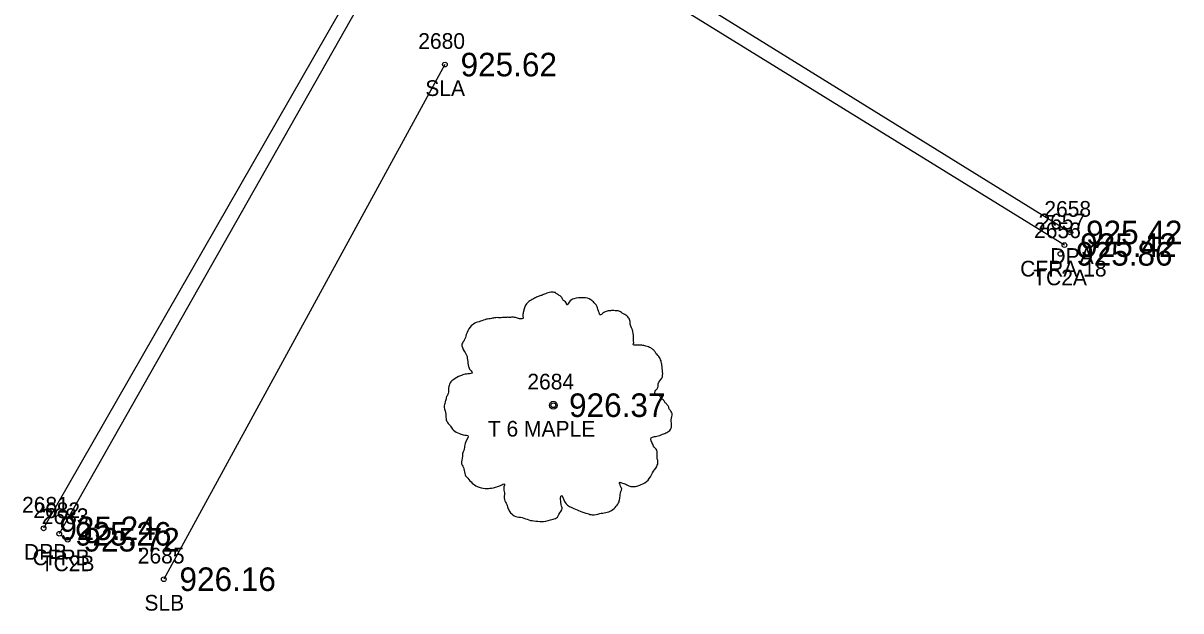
# Model space of a CAD drawing. Extents: x 1575382 to 1578175, y 1099175 to 1101955.
# Drawn here: x 1576884.4 to 1576958.1, y 1100231.2 to 1100268.6 of the extents above; entities that cross this region are included whole.
import ezdxf

# ---------------------------------------------------------------- set-up
doc = ezdxf.new("R2010")
doc.units = 0
for name, color, linetype in [('RD_EX_Conc', 7, 'Continuous'), ('RD_EX_Conc_txCode', 7, 'Continuous'), ('RD_EX_Driveway', 7, 'Continuous'), ('RD_EX_Driveway_txCode', 7, 'Continuous'), ('RD_EX_TX_Conc_ELEV', 7, 'Continuous'), ('RD_EX_TX_Driveway_ELEV', 7, 'Continuous'), ('RD_EX_TX_VEG_ELEV', 7, 'Continuous'), ('RD_EX_VEG', 7, 'Continuous'), ('RD_EX_VEG_txCode', 7, 'Continuous'), ('RD_SMD_Locator', 7, 'Continuous')]:
    doc.layers.add(name, color=color, linetype=linetype)

msp = doc.modelspace()

# ---------------------------------------------------------------- linework, layer by layer
at = {"layer": 'RD_EX_Conc'}
msp.add_lwpolyline([(1576950.686, 1100254.487), (1576921.564, 1100272.475), (1576929.602, 1100285.245), (1576929.528, 1100287.387), (1576927.709, 1100288.698), (1576922.308, 1100288.785), (1576916.503, 1100286.517), (1576913.006, 1100282.543), (1576886.711, 1100236.108)], dxfattribs=at)
at = {"layer": 'RD_EX_Driveway'}
msp.add_lwpolyline([(1576951.058, 1100255.291), (1576922.81, 1100272.792), (1576930.511, 1100285.101), (1576930.352, 1100287.763), (1576927.798, 1100289.531), (1576922.044, 1100289.43), (1576915.936, 1100287.07), (1576912.303, 1100282.866), (1576885.713, 1100236.458)], dxfattribs=at)
at = {"layer": 'RD_EX_VEG'}
msp.add_line((1576911.25, 1100265.977), (1576893.359, 1100233.218), dxfattribs=at)
for centre, radius in [((1576918.154, 1100244.295), 0.25), ((1576918.142, 1100244.276), 0.0001)]:
    msp.add_circle(centre, radius, dxfattribs=at)
for points in [[(1576918.286, 1100251.462), (1576917.986, 1100251.487), (1576917.661, 1100251.387), (1576917.411, 1100251.287), (1576917.187, 1100251.212), (1576916.962, 1100251.112), (1576916.662, 1100250.937), (1576916.437, 1100250.737), (1576916.312, 1100250.487), (1576916.262, 1100250.262), (1576916.212, 1100249.988), (1576916.212, 1100249.813), (1576916.087, 1100249.788), (1576915.937, 1100249.813), (1576915.687, 1100249.888), (1576915.437, 1100249.888), (1576915.187, 1100249.888), (1576914.838, 1100249.863), (1576914.488, 1100249.863), (1576914.213, 1100249.813), (1576913.888, 1100249.763), (1576913.513, 1100249.638), (1576913.163, 1100249.513), (1576912.863, 1100249.263), (1576912.614, 1100248.788), (1576912.489, 1100248.438), (1576912.339, 1100248.188), (1576912.489, 1100247.739), (1576912.664, 1100247.389), (1576912.688, 1100247.189), (1576912.763, 1100246.764), (1576912.863, 1100246.539), (1576912.988, 1100246.339), (1576912.913, 1100246.314), (1576912.539, 1100246.264), (1576912.239, 1100246.164), (1576911.814, 1100245.939), (1576911.589, 1100245.714), (1576911.489, 1100245.389), (1576911.464, 1100245.04), (1576911.364, 1100244.84), (1576911.289, 1100244.565), (1576911.264, 1100244.49), (1576911.214, 1100244.165), (1576911.314, 1100243.715), (1576911.339, 1100243.365), (1576911.464, 1100243.14), (1576911.614, 1100242.966), (1576911.789, 1100242.716), (1576912.189, 1100242.491), (1576912.514, 1100242.391), (1576912.713, 1100242.366), (1576912.539, 1100241.866), (1576912.489, 1100241.516), (1576912.364, 1100241.116), (1576912.364, 1100241.041), (1576912.314, 1100240.567), (1576912.464, 1100240.242), (1576912.539, 1100239.867), (1576912.713, 1100239.642), (1576912.988, 1100239.342), (1576913.313, 1100239.117), (1576913.813, 1100238.992), (1576914.213, 1100239.017), (1576914.788, 1100239.192), (1576915.037, 1100239.267), (1576915.012, 1100239.092), (1576915.037, 1100238.717), (1576915.037, 1100238.293), (1576915.187, 1100237.968), (1576915.287, 1100237.693), (1576915.437, 1100237.443), (1576915.762, 1100237.218), (1576916.162, 1100237.143), (1576916.587, 1100236.993), (1576917.037, 1100236.918), (1576917.536, 1100236.893), (1576918.136, 1100237.043), (1576918.411, 1100237.168), (1576918.511, 1100237.343), (1576918.711, 1100237.718), (1576918.661, 1100237.943), (1576918.686, 1100238.543), (1576918.786, 1100238.368), (1576918.961, 1100238.018), (1576919.461, 1100237.718), (1576919.86, 1100237.543), (1576920.335, 1100237.393), (1576920.635, 1100237.318), (1576921.11, 1100237.393), (1576921.485, 1100237.468), (1576921.859, 1100237.593), (1576922.159, 1100237.868), (1576922.334, 1100238.143), (1576922.384, 1100238.418), (1576922.459, 1100238.792), (1576922.509, 1100238.967)], [(1576922.509, 1100238.967), (1576922.434, 1100239.142), (1576922.384, 1100239.392), (1576922.459, 1100239.367), (1576922.634, 1100239.317), (1576922.909, 1100239.192), (1576923.134, 1100239.117), (1576923.459, 1100239.142), (1576923.734, 1100239.242), (1576924.183, 1100239.517), (1576924.458, 1100239.992), (1576924.733, 1100240.392), (1576924.808, 1100240.717), (1576924.758, 1100240.941), (1576924.733, 1100241.441), (1576924.533, 1100241.691), (1576924.483, 1100241.816), (1576924.383, 1100242.216), (1576924.458, 1100242.266), (1576924.733, 1100242.316), (1576925.108, 1100242.441), (1576925.383, 1100242.566), (1576925.608, 1100242.741), (1576925.683, 1100242.966), (1576925.658, 1100243.365), (1576925.708, 1100243.765), (1576925.633, 1100243.915), (1576925.533, 1100244.065), (1576925.458, 1100244.265), (1576925.308, 1100244.415), (1576925.208, 1100244.565), (1576925.108, 1100244.665), (1576924.983, 1100244.815), (1576924.808, 1100244.94), (1576924.658, 1100244.99), (1576924.608, 1100245.14), (1576924.758, 1100245.34), (1576924.808, 1100245.439), (1576924.833, 1100245.664), (1576925.058, 1100246.014), (1576925.108, 1100246.414), (1576925.058, 1100246.839), (1576925.008, 1100247.114), (1576924.858, 1100247.389), (1576924.658, 1100247.639), (1576924.533, 1100247.813), (1576924.358, 1100247.938), (1576924.034, 1100248.063), (1576923.784, 1100248.113), (1576923.434, 1100248.113), (1576923.234, 1100248.163), (1576923.259, 1100248.213), (1576923.259, 1100248.363), (1576923.259, 1100248.638), (1576923.184, 1100249.088), (1576923.034, 1100249.588), (1576923.034, 1100249.613), (1576922.934, 1100249.863), (1576922.709, 1100250.062), (1576922.534, 1100250.162), (1576922.334, 1100250.287), (1576922.084, 1100250.312), (1576921.785, 1100250.312), (1576921.51, 1100250.262), (1576921.31, 1100250.162), (1576921.135, 1100250.037), (1576921.06, 1100250.187), (1576920.96, 1100250.487), (1576920.91, 1100250.637), (1576920.76, 1100250.812), (1576920.535, 1100251.012), (1576920.085, 1100251.137), (1576919.461, 1100251.062), (1576919.161, 1100250.862), (1576919.011, 1100250.687), (1576918.961, 1100250.812), (1576918.761, 1100251.012), (1576918.661, 1100251.187), (1576918.486, 1100251.312), (1576918.336, 1100251.412), (1576918.236, 1100251.462)]]:
    msp.add_spline(points, degree=3, dxfattribs=at)
at = {"layer": 'RD_SMD_Locator'}
for centre in [(1576911.25, 1100265.977), (1576951.058, 1100255.291), (1576950.686, 1100254.487), (1576950.428, 1100253.929), (1576918.154, 1100244.295), (1576885.713, 1100236.458), (1576886.711, 1100236.108), (1576887.247, 1100235.73), (1576893.359, 1100233.218)]:
    msp.add_circle(centre, 0.15, dxfattribs=at)

# ---------------------------------------------------------------- texts
at = {"layer": 'RD_EX_Conc_txCode'}
for s, p in [('2657', (1576949.032, 1100255.487)), ('2656', (1576948.751, 1100254.929)), ('CFRA 18', (1576947.867, 1100252.487)), ('TC2A', (1576948.696, 1100251.929)), ('2682', (1576885.058, 1100237.108)), ('2683', (1576885.594, 1100236.73)), ('CFRB', (1576885.01, 1100234.108)), ('TC2B', (1576885.531, 1100233.73))]:
    msp.add_text(s, height=1, dxfattribs=at).set_placement(p)
at = {"layer": 'RD_EX_Driveway_txCode'}
for s, p in [('2658', (1576949.404, 1100256.291)), ('DPA', (1576949.79, 1100253.291)), ('2681', (1576884.343, 1100237.458)), ('DPB', (1576884.461, 1100234.458))]:
    msp.add_text(s, height=1, dxfattribs=at).set_placement(p)
at = {"layer": 'RD_EX_TX_Conc_ELEV'}
for s, p in [('925.86', (1576951.428, 1100253.179)), ('925.42', (1576951.686, 1100253.737)), ('925.26', (1576887.711, 1100235.358)), ('925.72', (1576888.247, 1100234.98))]:
    msp.add_text(s, height=1.5, dxfattribs=at).set_placement(p)
at = {"layer": 'RD_EX_TX_Driveway_ELEV'}
for s, p in [('925.42', (1576952.058, 1100254.541)), ('925.24', (1576886.713, 1100235.708))]:
    msp.add_text(s, height=1.5, dxfattribs=at).set_placement(p)
at = {"layer": 'RD_EX_TX_VEG_ELEV'}
for s, p in [('925.62', (1576912.25, 1100265.227)), ('926.37', (1576919.154, 1100243.545)), ('926.16', (1576894.359, 1100232.468))]:
    msp.add_text(s, height=1.5, dxfattribs=at).set_placement(p)
at = {"layer": 'RD_EX_VEG_txCode'}
for s, p in [('2680', (1576909.557, 1100266.977)), ('SLA', (1576910.006, 1100263.977)), ('2684', (1576916.501, 1100245.295)), ('T 6 MAPLE', (1576913.985, 1100242.295)), ('2685', (1576891.705, 1100234.218)), ('SLB', (1576892.13, 1100231.218))]:
    msp.add_text(s, height=1, dxfattribs=at).set_placement(p)

doc.saveas('drawing.dxf')
